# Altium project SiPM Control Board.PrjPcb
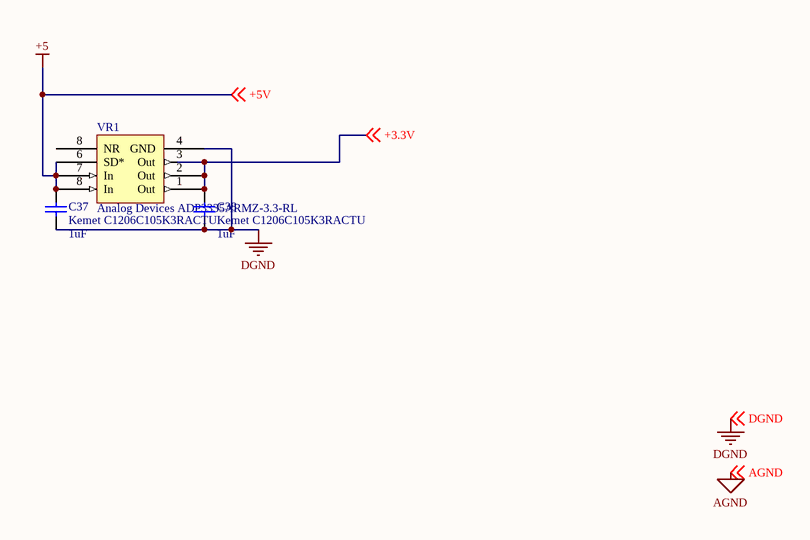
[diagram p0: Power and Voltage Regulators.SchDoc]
9 sheets, 76 parts. Net scope: global (net labels, ports and power ports of the same name join across sheets).
Board file: Prototype1.PcbDoc
Sheets:
  Power and Voltage Regulators.SchDoc
  AD5535.SchDoc
  AD5535 Power Regulators.SchDoc
  AD7314.SchDoc
  EEPROM.SchDoc
  CP2201.SchDoc
  AD7928.SchDoc
  FPGA.SchDoc
  Backplane Connector.SchDoc

## Sheet Power and Voltage Regulators.SchDoc
size A

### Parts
C37  Kemet C1206C105K3RACTU  value 1uF  [C1206]
C38  Kemet C1206C105K3RACTU  value 1uF  [C1206]
VR1  Analog Devices ADP3335ARMZ-3.3-RL  [RM-8]

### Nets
+5: C37.2 VR1.6(SD*) VR1.7(In) VR1.8(In) ; off-sheet +5V  [also labelled +5V]
DGND: C37.1 C38.1 VR1.4(GND) ; off-sheet DGND
+3.3V: C38.2 VR1.1(Out) VR1.2(Out) VR1.3(Out) ; off-sheet +3.3V

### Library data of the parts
C37 C38 = Cap: Capacitor
VR1 = ADP3335

## Sheet AD5535.SchDoc
size A
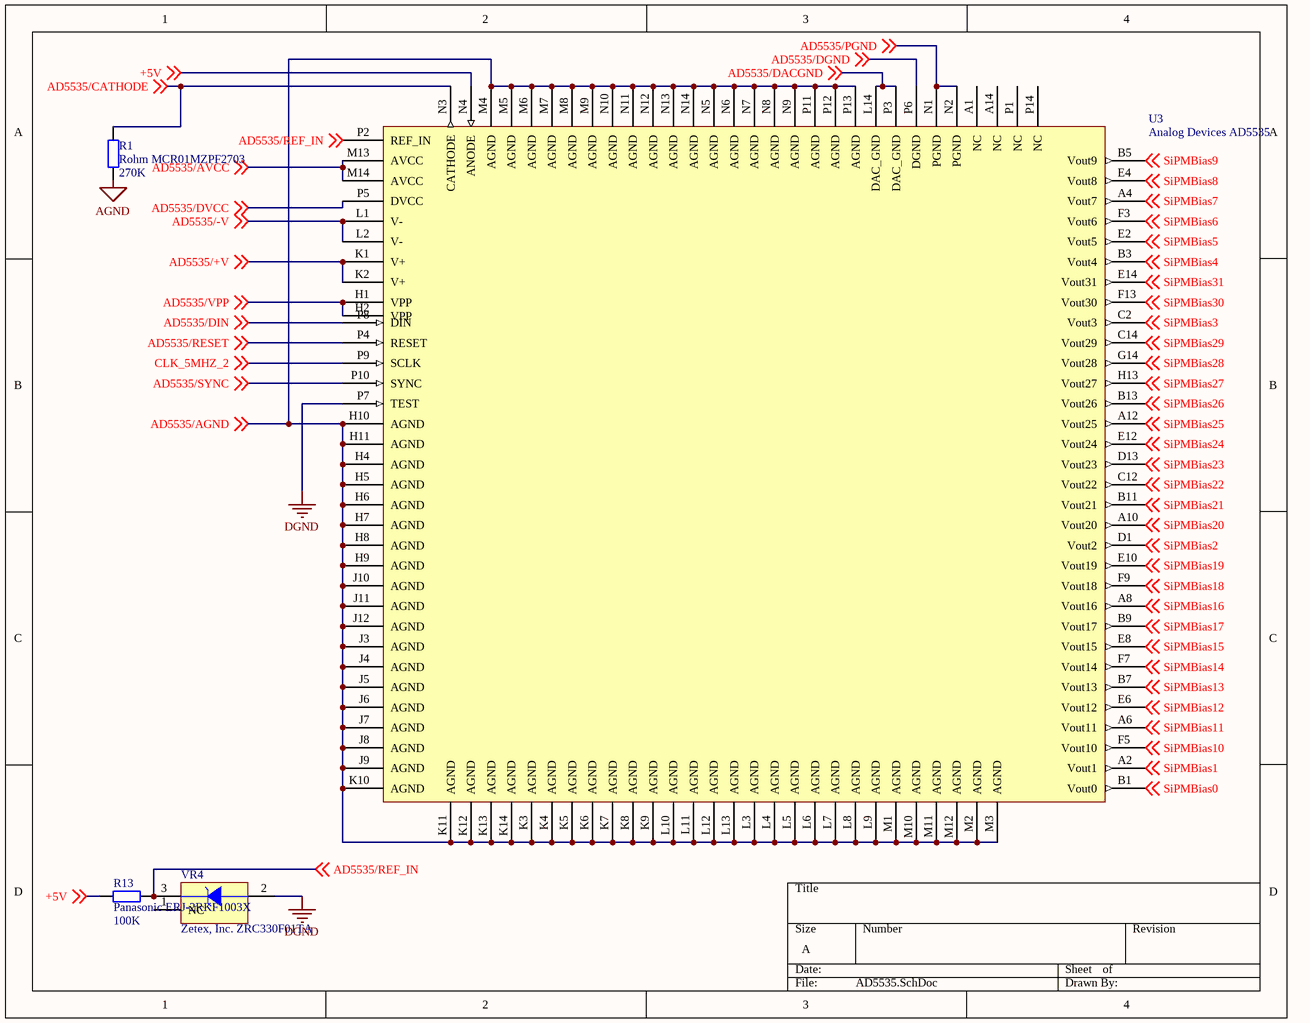
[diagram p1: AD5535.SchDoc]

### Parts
R1  Rohm MCR01MZPF2703  value 270K  [0402]
R13  Panasonic ERJ-2RKF1003X  value 100K  [1005[0402]]
U3  Analog Devices AD5535  [BC-124]
VR4  Zetex, Inc. ZRC330F01TA  [SOT23]

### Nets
+5V: R13.1 U3.K1(V+) U3.K2(V+) U3.M13(AVCC) U3.M14(AVCC) U3.N4(ANODE) U3.P5(DVCC) ; off-sheet AD5535/+V, off-sheet AD5535/AVCC, off-sheet AD5535/DVCC, off-sheet +5V  [also labelled AD5535/+V, AD5535/AVCC, AD5535/DVCC]  [project net +5]
AGND: R1.1 U3.H4(AGND) U3.H5(AGND) U3.H6(AGND) U3.H7(AGND) U3.H8(AGND) U3.H9(AGND) U3.H10(AGND) U3.H11(AGND) U3.J3(AGND) U3.J4(AGND) U3.J5(AGND) U3.J6(AGND) U3.J7(AGND) U3.J8(AGND) U3.J9(AGND) U3.J10(AGND) U3.J11(AGND) U3.J12(AGND) U3.K3(AGND) U3.K4(AGND) U3.K5(AGND) U3.K6(AGND) U3.K7(AGND) U3.K8(AGND) U3.K9(AGND) U3.K10(AGND) U3.K11(AGND) U3.K12(AGND) U3.K13(AGND) U3.K14(AGND) U3.L3(AGND) U3.L4(AGND) U3.L5(AGND) U3.L6(AGND) U3.L7(AGND) U3.L8(AGND) U3.L9(AGND) U3.L10(AGND) U3.L11(AGND) U3.L12(AGND) U3.L13(AGND) U3.L14(DAC_GND) U3.M1(AGND) U3.M2(AGND) U3.M3(AGND) U3.M4(AGND) U3.M5(AGND) U3.M6(AGND) U3.M7(AGND) U3.M8(AGND) U3.M9(AGND) U3.M10(AGND) U3.M11(AGND) U3.M12(AGND) U3.N1(PGND) U3.N2(PGND) U3.N5(AGND) U3.N6(AGND) U3.N7(AGND) U3.N8(AGND) U3.N9(AGND) U3.N10(AGND) U3.N11(AGND) U3.N12(AGND) U3.N13(AGND) U3.N14(AGND) U3.P3(DAC_GND) U3.P11(AGND) U3.P12(AGND) U3.P13(AGND) ; off-sheet AD5535/AGND, off-sheet AD5535/DACGND, off-sheet AD5535/PGND  [also labelled AD5535/AGND, AD5535/DACGND, AD5535/PGND]
DGND: U3.P6(DGND) U3.P7(TEST) VR4.2(GND) ; off-sheet AD5535/DGND  [also labelled AD5535/DGND]
AD5535/-V: U3.L1(V-) U3.L2(V-) ; off-sheet AD5535/-V  [project net -5V]
AD5535/CATHODE: R1.2 U3.N3(CATHODE) ; off-sheet AD5535/CATHODE
AD5535/DIN: U3.P8(DIN) ; off-sheet AD5535/DIN
AD5535/REF_IN: R13.2 U3.P2(REF_IN) VR4.3(VR) ; off-sheet AD5535/REF_IN
AD5535/RESET: U3.P4(RESET) ; off-sheet AD5535/RESET
AD5535/SYNC: U3.P10(SYNC) ; off-sheet AD5535/SYNC
AD5535/VPP: U3.H1(VPP) U3.H2(VPP) ; off-sheet AD5535/VPP  [project net +210V]
CLK_5MHZ_2: U3.P9(SCLK) ; off-sheet CLK_5MHZ_2
SiPMBias0: U3.B1(Vout0) ; off-sheet SiPMBias0
SiPMBias1: U3.A2(Vout1) ; off-sheet SiPMBias1
SiPMBias2: U3.D1(Vout2) ; off-sheet SiPMBias2
SiPMBias3: U3.C2(Vout3) ; off-sheet SiPMBias3
SiPMBias4: U3.B3(Vout4) ; off-sheet SiPMBias4
SiPMBias5: U3.E2(Vout5) ; off-sheet SiPMBias5
SiPMBias6: U3.F3(Vout6) ; off-sheet SiPMBias6
SiPMBias7: U3.A4(Vout7) ; off-sheet SiPMBias7
SiPMBias8: U3.E4(Vout8) ; off-sheet SiPMBias8
SiPMBias9: U3.B5(Vout9) ; off-sheet SiPMBias9
SiPMBias10: U3.F5(Vout10) ; off-sheet SiPMBias10
SiPMBias11: U3.A6(Vout11) ; off-sheet SiPMBias11
SiPMBias12: U3.E6(Vout12) ; off-sheet SiPMBias12
SiPMBias13: U3.B7(Vout13) ; off-sheet SiPMBias13
SiPMBias14: U3.F7(Vout14) ; off-sheet SiPMBias14
SiPMBias15: U3.E8(Vout15) ; off-sheet SiPMBias15
SiPMBias16: U3.A8(Vout16) ; off-sheet SiPMBias16
SiPMBias17: U3.B9(Vout17) ; off-sheet SiPMBias17
SiPMBias18: U3.F9(Vout18) ; off-sheet SiPMBias18
SiPMBias19: U3.E10(Vout19) ; off-sheet SiPMBias19
SiPMBias20: U3.A10(Vout20) ; off-sheet SiPMBias20
SiPMBias21: U3.B11(Vout21) ; off-sheet SiPMBias21
SiPMBias22: U3.C12(Vout22) ; off-sheet SiPMBias22
SiPMBias23: U3.D13(Vout23) ; off-sheet SiPMBias23
SiPMBias24: U3.E12(Vout24) ; off-sheet SiPMBias24
SiPMBias25: U3.A12(Vout25) ; off-sheet SiPMBias25
SiPMBias26: U3.B13(Vout26) ; off-sheet SiPMBias26
SiPMBias27: U3.H13(Vout27) ; off-sheet SiPMBias27
SiPMBias28: U3.G14(Vout28) ; off-sheet SiPMBias28
SiPMBias29: U3.C14(Vout29) ; off-sheet SiPMBias29
SiPMBias30: U3.F13(Vout30) ; off-sheet SiPMBias30
SiPMBias31: U3.E14(Vout31) ; off-sheet SiPMBias31

Not connected (* = marked no-connect by the designer): U3 A1(NC) A14(NC) P1(NC) P14(NC); VR4 1(NC)

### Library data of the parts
R1 R13 = Res2: Resistor
U3 = AD5535
VR4 = LM4040DIM3-2.5: Precision Micropower Shunt Voltage Reference; Note: Pin 3 must be left floating or connected to pin 2.

## Sheet AD5535 Power Regulators.SchDoc
size A
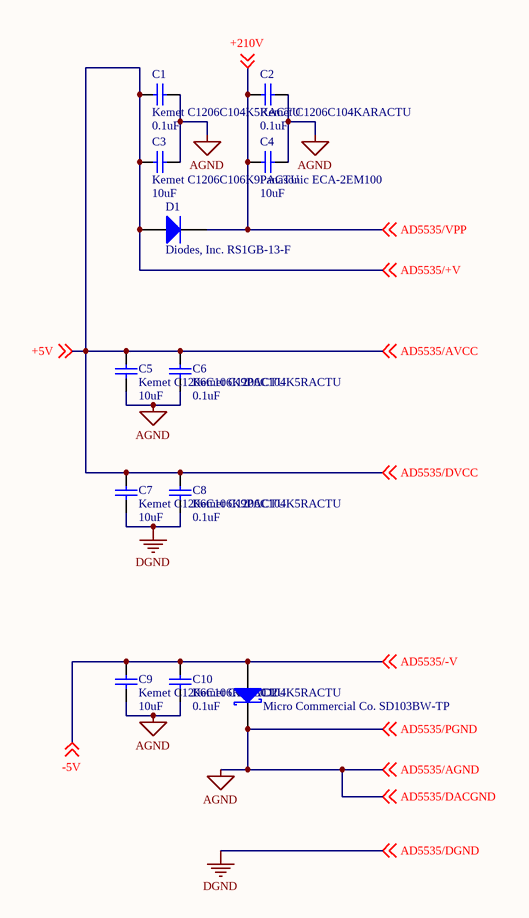
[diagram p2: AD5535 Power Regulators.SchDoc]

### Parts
C1  Kemet C1206C104K5RACTU  value 0.1uF  [C1206]
C2  Kemet C1206C104KARACTU  value 0.1uF  [C1206]
C3  Kemet C1206C106K9PACTU  value 10uF  [C1206]
C4  Panasonic ECA-2EM100  value 10uF  [CAPPR5-10x16]
C5  Kemet C1206C106K9PACTU  value 10uF  [C1206]
C6  Kemet C1206C104K5RACTU  value 0.1uF  [C1206]
C7  Kemet C1206C106K9PACTU  value 10uF  [C1206]
C8  Kemet C1206C104K5RACTU  value 0.1uF  [C1206]
C9  Kemet C1206C106K9PACTU  value 10uF  [C1206]
C10  Kemet C1206C104K5RACTU  value 0.1uF  [C1206]
D1  Diodes, Inc. RS1GB-13-F  [SMB]
D2  Micro Commercial Co. SD103BW-TP  [425]

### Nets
+5V: C1.1 C3.1 C5.2 C6.2 C7.2 C8.2 D1.1(A) ; off-sheet +5V, off-sheet AD5535/+V, off-sheet AD5535/AVCC, off-sheet AD5535/DVCC  [also labelled AD5535/+V, AD5535/AVCC, AD5535/DVCC]  [project net +5]
AGND: C1.2 C2.2 C3.2 C4.2 C5.1 C6.1 C9.1 C10.1 D2.2(K) ; off-sheet AD5535/PGND, off-sheet AD5535/AGND, off-sheet AD5535/DACGND  [also labelled AD5535/AGND, AD5535/DACGND, AD5535/PGND]
DGND: C7.1 C8.1 ; off-sheet AD5535/DGND  [also labelled AD5535/DGND]
+210V: C2.1 C4.1 D1.2(K) ; off-sheet AD5535/VPP, off-sheet +210V  [also labelled AD5535/VPP]
-5V: C9.2 C10.2 D2.1(A) ; off-sheet AD5535/-V, off-sheet -5V  [also labelled AD5535/-V]

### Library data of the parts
C1-C10 = Cap: Capacitor
D1 = Diode: Default Diode
D2 = D Schottky: Schottky Diode

## Sheet AD7314.SchDoc
size A
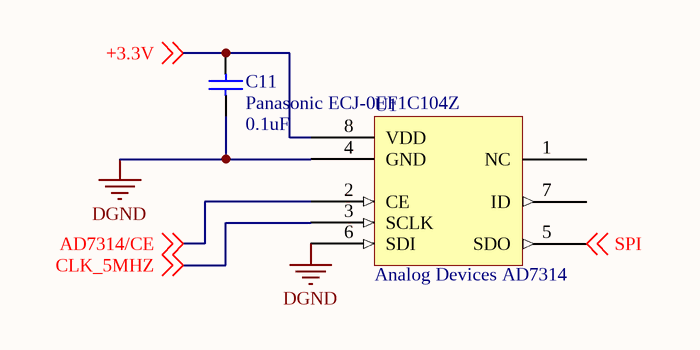
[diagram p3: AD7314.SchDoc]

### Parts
C11  Panasonic ECJ-0EF1C104Z  value 0.1uF  [0402]
U1  Analog Devices AD7314  [RM-8]

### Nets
DGND: C11.1 U1.4(GND) U1.6(SDI)
+3.3V: C11.2 U1.8(VDD) ; off-sheet +3.3V
AD7314/CE: U1.2(CE) ; off-sheet AD7314/CE
CLK_5MHZ: U1.3(SCLK) ; off-sheet CLK_5MHZ
SPI: U1.5(SDO) ; off-sheet SPI

Not connected (* = marked no-connect by the designer): U1 1(NC) 7(ID)

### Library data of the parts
C11 = Cap: Capacitor
U1 = AD7314

## Sheet EEPROM.SchDoc
size A
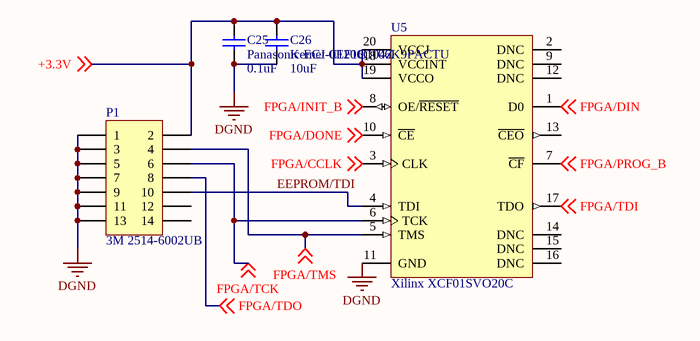
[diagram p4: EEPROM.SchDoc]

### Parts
C25  Panasonic ECJ-0EF1C104Z  value 0.1uF  [0402]
C26  Kemet C1206C106K9PACTU  value 10uF  [C1206]
P1  3M 2514-6002UB  [HDR2X7]
U5  Xilinx XCF01SVO20C  [VO20_N]

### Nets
DGND: C25.1 C26.1 P1.1 P1.3 P1.5 P1.7 P1.9 P1.11 P1.13 U5.11(GND)
+3.3V: C25.2 C26.2 P1.2 U5.18(VCCINT) U5.19(VCCO) U5.20(VCCJ) ; off-sheet +3.3V
EEPROM/TDI: P1.10 U5.4(TDI)
FPGA/CCLK: U5.3(CLK) ; off-sheet FPGA/CCLK
FPGA/DIN: U5.1(D0) ; off-sheet FPGA/DIN
FPGA/DONE: U5.10(~{CE}) ; off-sheet FPGA/DONE
FPGA/INIT_B: U5.8(OE/~{RESET}) ; off-sheet FPGA/INIT_B
FPGA/PROG_B: U5.7(~{CF}) ; off-sheet FPGA/PROG_B
FPGA/TCK: P1.6 U5.6(TCK) ; off-sheet FPGA/TCK
FPGA/TDI: U5.17(TDO) ; off-sheet FPGA/TDI
FPGA/TDO: P1.8 ; off-sheet FPGA/TDO
FPGA/TMS: P1.4 U5.5(TMS) ; off-sheet FPGA/TMS

Not connected (* = marked no-connect by the designer): P1 12 14; U5 2(DNC) 9(DNC) 12(DNC) 13(~{CEO}) 14(DNC) 15(DNC) 16(DNC)

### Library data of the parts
C25 C26 = Cap: Capacitor
P1 = Header 7X2: Header, 7-Pin, Dual row
U5 = XCF01SVO20C: XCF00S Series, Platform Flash In-System Programmable Configuration 3.3V PROM, 20-Pin TSOP, 1-Megabit, Commercial Grade

## Sheet CP2201.SchDoc
size A
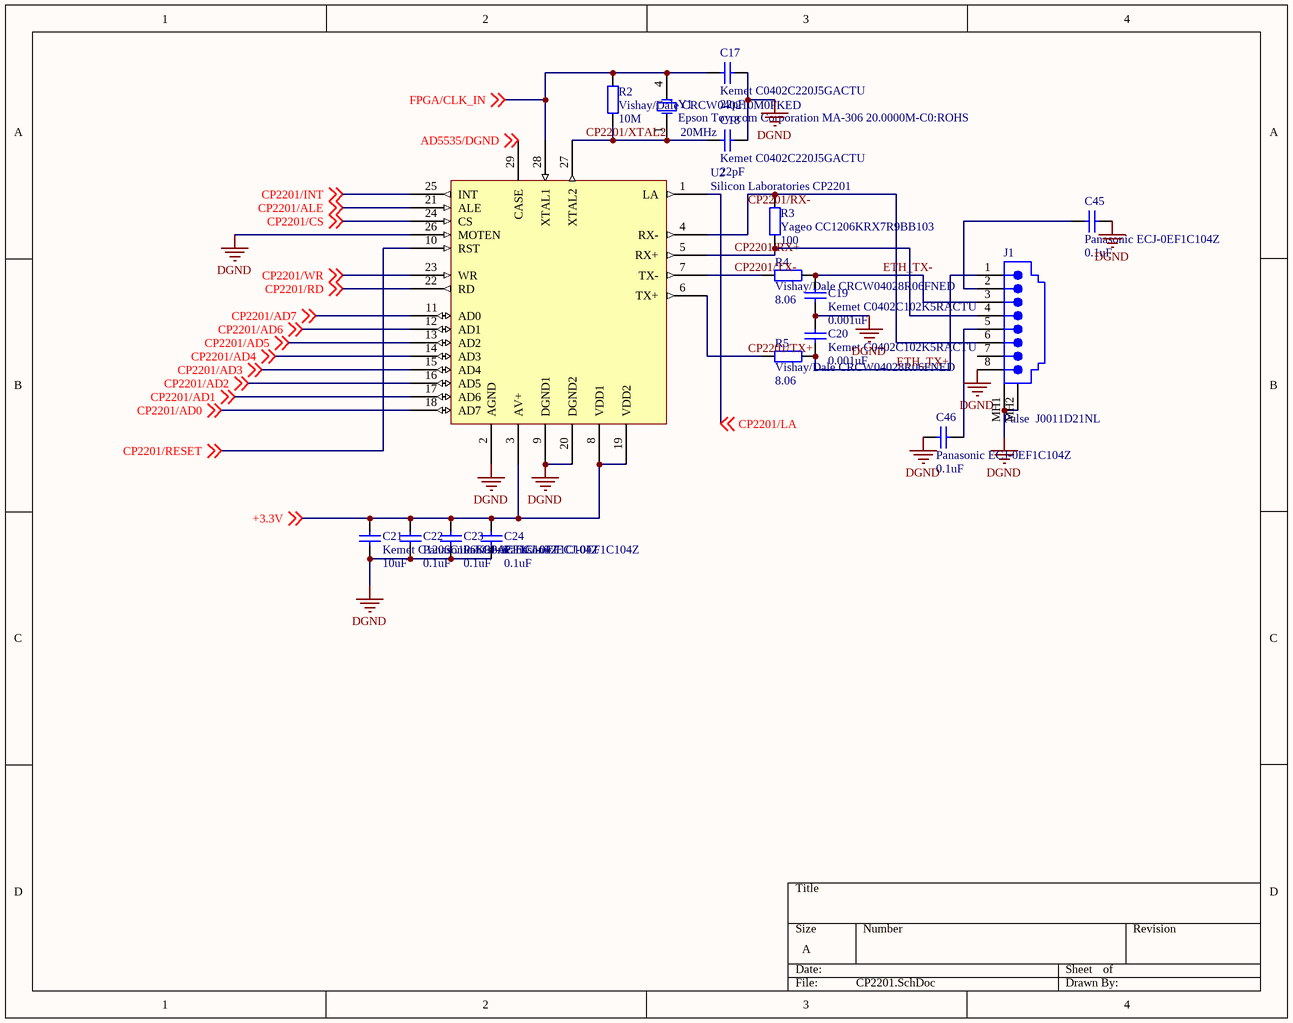
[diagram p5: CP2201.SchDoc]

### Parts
C17  Kemet C0402C220J5GACTU  value 22pF  [0402]
C18  Kemet C0402C220J5GACTU  value 22pF  [0402]
C19  Kemet C0402C102K5RACTU  value 0.001uF  [0402]
C20  Kemet C0402C102K5RACTU  value 0.001uF  [0402]
C21  Kemet C1206C106K9PACTU  value 10uF  [C1206]
C22  Panasonic ECJ-0EF1C104Z  value 0.1uF  [0402]
C23  Panasonic ECJ-0EF1C104Z  value 0.1uF  [0402]
C24  Panasonic ECJ-0EF1C104Z  value 0.1uF  [0402]
C45  Panasonic ECJ-0EF1C104Z  value 0.1uF  [0402]
C46  Panasonic ECJ-0EF1C104Z  value 0.1uF  [0402]
J1  Pulse  J0011D21NL  [43249-8925]
R2  Vishay/Dale CRCW040210M0FKED  value 10M  [1005[0402]]
R3  Yageo CC1206KRX7R9BB103  value 100  [1005[0402]]
R4  Vishay/Dale CRCW04028R06FNED  value 8.06  [1005[0402]]
R5  Vishay/Dale CRCW04028R06FNED  value 8.06  [1005[0402]]
U2  Silicon Laboratories CP2201  [QFN50P500X500-28V1N]
Y1  Epson Toyocom Corporation MA-306 20.0000M-C0:ROHS  Frequency: 20MHz  [DSO-N4]

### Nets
DGND: C17.2 C18.2 C19.1 C20.2 C21.1 C22.1 C23.1 C24.1 C45.2 C46.1 J1.8 J1.MH1(Shield) J1.MH2(Shield) U2.2(AGND) U2.9(DGND1) U2.20(DGND2) U2.26(MOTEN) U2.29(CASE) ; off-sheet AD5535/DGND  [also labelled AD5535/DGND]
+3.3V: C21.2 C22.2 C23.2 C24.2 U2.3(AV+) U2.8(VDD1) U2.19(VDD2) ; off-sheet +3.3V
CP2201/AD0: U2.18(AD7) ; off-sheet CP2201/AD0
CP2201/AD1: U2.17(AD6) ; off-sheet CP2201/AD1
CP2201/AD2: U2.16(AD5) ; off-sheet CP2201/AD2
CP2201/AD3: U2.15(AD4) ; off-sheet CP2201/AD3
CP2201/AD4: U2.14(AD3) ; off-sheet CP2201/AD4
CP2201/AD5: U2.13(AD2) ; off-sheet CP2201/AD5
CP2201/AD6: U2.12(AD1) ; off-sheet CP2201/AD6
CP2201/AD7: U2.11(AD0) ; off-sheet CP2201/AD7
CP2201/ALE: U2.21(ALE) ; off-sheet CP2201/ALE
CP2201/CS: U2.24(CS) ; off-sheet CP2201/CS
CP2201/INT: U2.25(INT) ; off-sheet CP2201/INT
CP2201/LA: U2.1(LA) ; off-sheet CP2201/LA
CP2201/RD: U2.22(RD) ; off-sheet CP2201/RD
CP2201/RESET: U2.10(RST) ; off-sheet CP2201/RESET
CP2201/RX+: J1.4 R3.1 U2.5(RX+)
CP2201/RX-: J1.6 R3.2 U2.4(RX-)
CP2201/TX+: R5.1 U2.6(TX+)
CP2201/TX-: R4.1 U2.7(TX-)
CP2201/WR: U2.23(WR) ; off-sheet CP2201/WR
CP2201/XTAL2: C18.1 R2.2 U2.27(XTAL2) Y1.1(OSC1)
ETH_TX+: C20.1 J1.1 R5.2
ETH_TX-: C19.2 J1.3 R4.2
FPGA/CLK_IN: C17.1 R2.1 U2.28(XTAL1) Y1.4(OSC2) ; off-sheet FPGA/CLK_IN
NetC45_1: C45.1 J1.2
NetC46_2: C46.2 J1.5

Not connected (* = marked no-connect by the designer): J1 7

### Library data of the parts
C17-C24 C45 C46 = Cap: Capacitor
J1 = 43249-8925: Right Angle, Low Profile, with top Panel Grounding Tabs, Shielded PCB Jack; Ports: 1; Positions/Loaded: Port1 - 8/8; PerformanceCategory: 3/4; PCB_Mounting: Thru-Hole; DrillSize: Nominal, Rounded to nearest 0.05mm; PCB_Layout: Complies with Manufacturer's Recommendation.
R2-R5 = Res2: Resistor
U2 = CP2201
Y1 = XTAL: Crystal Oscillator

## Sheet AD7928.SchDoc
size A
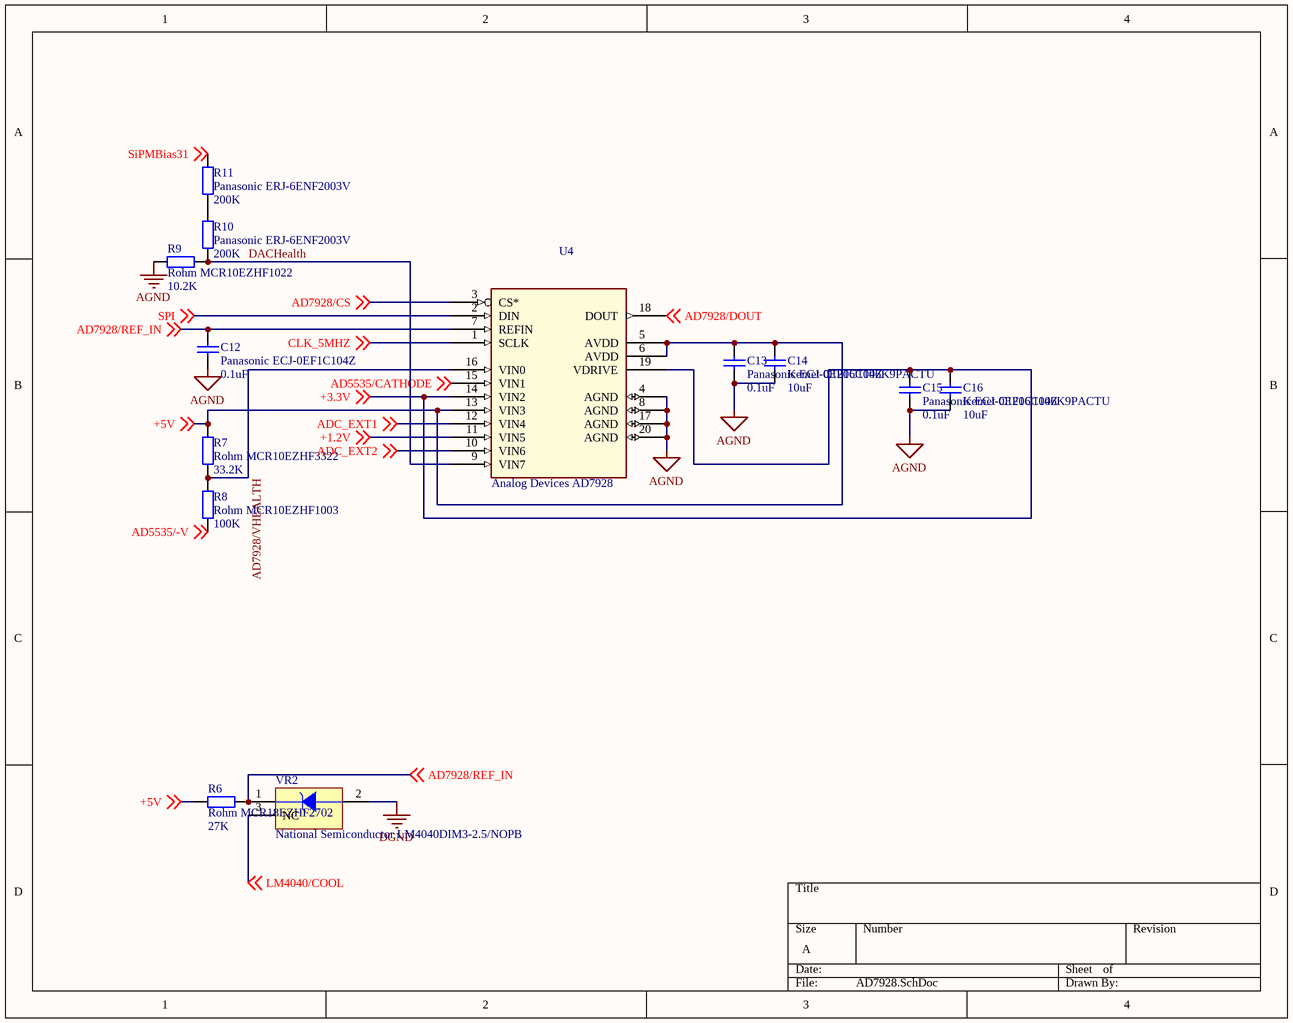
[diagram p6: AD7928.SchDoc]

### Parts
C12  Panasonic ECJ-0EF1C104Z  value 0.1uF  [0402]
C13  Panasonic ECJ-0EF1C104Z  value 0.1uF  [0402]
C14  Kemet C1206C106K9PACTU  value 10uF  [C1206]
C15  Panasonic ECJ-0EF1C104Z  value 0.1uF  [0402]
C16  Kemet C1206C106K9PACTU  value 10uF  [C1206]
R6  Rohm MCR18EZHF2702  value 27K  [3216[1206]]
R7  Rohm MCR10EZHF3322  value 33.2K  [2012[0805]]
R8  Rohm MCR10EZHF1003  value 100K  [2012[0805]]
R9  Rohm MCR10EZHF1022  value 10.2K  [2012[0805]]
R10  Panasonic ERJ-6ENF2003V  value 200K  [2012[0805]]
R11  Panasonic ERJ-6ENF2003V  value 200K  [2012[0805]]
U4  Analog Devices AD7928  [RU-20]
VR2  National Semiconductor LM4040DIM3-2.5/NOPB  [M03B]

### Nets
+5V: C13.2 C14.2 R6.1 R7.2 U4.5(AVDD) U4.6(AVDD) U4.13(VIN3) ; off-sheet +5V  [project net +5]
AGND: C12.1 C13.1 C14.1 C15.1 C16.1 R9.2 U4.4(AGND) U4.8(AGND) U4.17(AGND) U4.20(AGND)
DGND: VR2.2(V-)
+1.2V: U4.11(VIN5) ; off-sheet +1.2V
+3.3V: C15.2 C16.2 U4.14(VIN2) U4.19(VDRIVE) ; off-sheet +3.3V
AD5535/-V: R8.1 ; off-sheet AD5535/-V  [project net -5V]
AD5535/CATHODE: U4.15(VIN1) ; off-sheet AD5535/CATHODE
AD7928/CS: U4.3(CS*) ; off-sheet AD7928/CS
AD7928/DOUT: U4.18(DOUT) ; off-sheet AD7928/DOUT
AD7928/REF_IN: C12.2 R6.2 U4.7(REFIN) VR2.1(V+) ; off-sheet AD7928/REF_IN
AD7928/VHEALTH: R7.1 R8.2 U4.16(VIN0)
ADC_EXT1: U4.12(VIN4) ; off-sheet ADC_EXT1
ADC_EXT2: U4.10(VIN6) ; off-sheet ADC_EXT2
CLK_5MHZ: U4.1(SCLK) ; off-sheet CLK_5MHZ
DACHealth: R9.1 R10.1 U4.9(VIN7)
LM4040/COOL: VR2.3(NC) ; off-sheet LM4040/COOL
SiPMBias31: R11.2 ; off-sheet SiPMBias31
SPI: U4.2(DIN) ; off-sheet SPI
NetR10_2: R10.2 R11.1

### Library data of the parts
C12-C16 = Cap: Capacitor
R6-R11 = Res2: Resistor
U4 = AD7928BRU-REEL7: SlotXofY: SYM 1 OF 1
VR2 = LM4040DIM3-2.5: as VR4 on sheet AD5535

## Sheet FPGA.SchDoc
size A
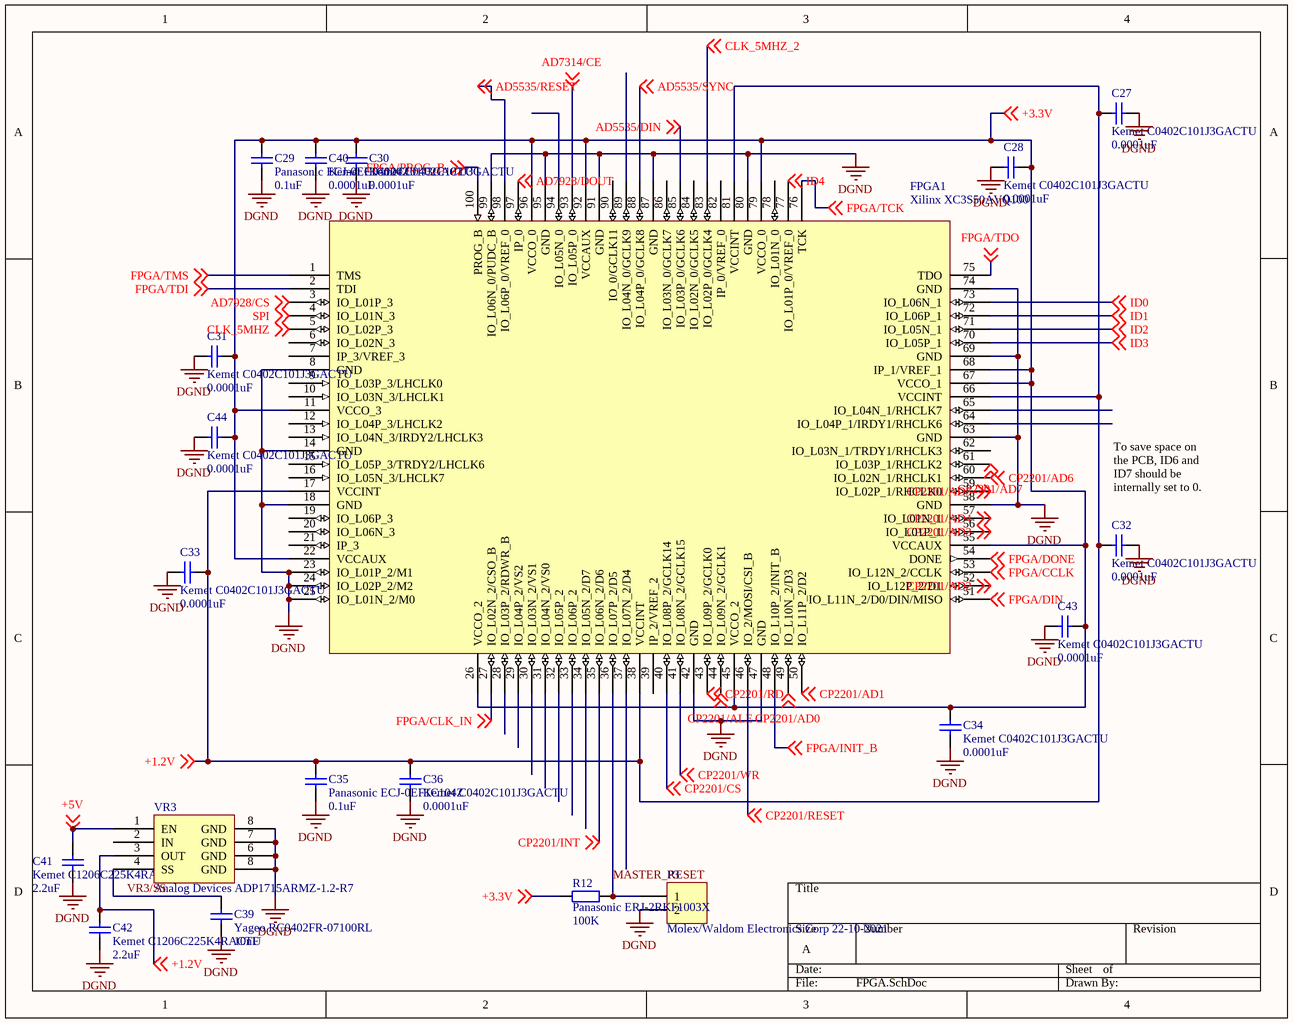
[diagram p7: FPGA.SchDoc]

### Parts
C27  Kemet C0402C101J3GACTU  value 0.0001uF  [0402]
C28  Kemet C0402C101J3GACTU  value 0.0001uF  [0402]
C29  Panasonic ECJ-0EF1C104Z  value 0.1uF  [0402]
C30  Kemet C0402C101J3GACTU  value 0.0001uF  [0402]
C31  Kemet C0402C101J3GACTU  value 0.0001uF  [0402]
C32  Kemet C0402C101J3GACTU  value 0.0001uF  [0402]
C33  Kemet C0402C101J3GACTU  value 0.0001uF  [0402]
C34  Kemet C0402C101J3GACTU  value 0.0001uF  [0402]
C35  Panasonic ECJ-0EF1C104Z  value 0.1uF  [0402]
C36  Kemet C0402C101J3GACTU  value 0.0001uF  [0402]
C39  Yageo RC0402FR-07100RL  value 10nF  [C1206]
C40  Kemet C0402C101J3GACTU  value 0.0001uF  [0402]
C41  Kemet C1206C225K4RACTU  value 2.2uF  [C1206]
C42  Kemet C1206C225K4RACTU  value 2.2uF  [C1206]
C43  Kemet C0402C101J3GACTU  value 0.0001uF  [0402]
C44  Kemet C0402C101J3GACTU  value 0.0001uF  [0402]
FPGA1  Xilinx XC3S50AVQ100  [VQ100_L]
P3  Molex/Waldom Electronics Corp 22-10-2021  [HDR1X2]
R12  Panasonic ERJ-2RKF1003X  value 100K  [1005[0402]]
VR3  Analog Devices ADP1715ARMZ-1.2-R7  [RM-8]

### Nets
+5V: C41.2 VR3.1(EN) ; off-sheet +5V  [project net +5]
DGND: C27.1 C28.1 C29.1 C30.1 C31.1 C32.1 C33.1 C34.1 C35.1 C36.1 C39.1 C40.1 C41.1 C42.1 C43.2 C44.1 FPGA1.8(GND) FPGA1.14(GND) FPGA1.18(GND) FPGA1.23(IO_L01P_2/M1) FPGA1.24(IO_L02P_2/M2) FPGA1.25(IO_L01N_2/M0) FPGA1.42(GND) FPGA1.47(GND) FPGA1.58(GND) FPGA1.63(GND) FPGA1.69(GND) FPGA1.74(GND) FPGA1.80(GND) FPGA1.87(GND) FPGA1.91(GND) FPGA1.95(GND) FPGA1.99(IO_L06N_0/PUDC_B) P3.2 VR3.6(GND) VR3.7(GND) VR3.8(GND)
+1.2V: C27.2 C32.2 C33.2 C35.2 C36.2 C42.2 FPGA1.17(VCCINT) FPGA1.38(VCCINT) FPGA1.66(VCCINT) FPGA1.81(VCCINT) VR3.3(OUT) ; off-sheet +1.2V
+3.3V: C28.2 C29.2 C30.2 C31.2 C34.2 C40.2 C43.1 C44.2 FPGA1.11(VCCO_3) FPGA1.22(VCCAUX) FPGA1.26(VCCO_2) FPGA1.45(VCCO_2) FPGA1.55(VCCAUX) FPGA1.67(VCCO_1) FPGA1.68(IP_1/VREF_1) FPGA1.79(VCCO_0) FPGA1.92(VCCAUX) FPGA1.96(VCCO_0) R12.1 ; off-sheet +3.3V
AD5535/DIN: FPGA1.85(IO_L03P_0/GCLK6) ; off-sheet AD5535/DIN
AD5535/RESET: FPGA1.98(IO_L06P_0/VREF_0) ; off-sheet AD5535/RESET
AD5535/SYNC: FPGA1.88(IO_L04P_0/GCLK8) ; off-sheet AD5535/SYNC
AD7314/CE: FPGA1.93(IO_L05P_0) ; off-sheet AD7314/CE
AD7928/CS: FPGA1.3(IO_L01P_3) ; off-sheet AD7928/CS
AD7928/DOUT: FPGA1.97(IP_0) ; off-sheet AD7928/DOUT
CLK_5MHZ: FPGA1.5(IO_L02P_3) ; off-sheet CLK_5MHZ
CLK_5MHZ_2: FPGA1.83(IO_L02P_0/GCLK4) ; off-sheet CLK_5MHZ_2
CP2201/AD0: FPGA1.49(IO_L10N_2/D3) ; off-sheet CP2201/AD0
CP2201/AD1: FPGA1.50(IO_L11P_2/D2) ; off-sheet CP2201/AD1
CP2201/AD2: FPGA1.52(IO_L12P_2/D1) ; off-sheet CP2201/AD2
CP2201/AD3: FPGA1.56(IO_L01P_1) ; off-sheet CP2201/AD3
CP2201/AD4: FPGA1.57(IO_L01N_1) ; off-sheet CP2201/AD4
CP2201/AD5: FPGA1.59(IO_L02P_1/RHCLK0) ; off-sheet CP2201/AD5
CP2201/AD6: FPGA1.60(IO_L02N_1/RHCLK1) ; off-sheet CP2201/AD6
CP2201/AD7: FPGA1.61(IO_L03P_1/RHCLK2) ; off-sheet CP2201/AD7
CP2201/ALE: FPGA1.44(IO_L09N_2/GCLK1) ; off-sheet CP2201/ALE
CP2201/CS: FPGA1.40(IO_L08P_2/GCLK14) ; off-sheet CP2201/CS
CP2201/INT: FPGA1.35(IO_L06N_2/D6) ; off-sheet CP2201/INT
CP2201/RD: FPGA1.43(IO_L09P_2/GCLK0) ; off-sheet CP2201/RD
CP2201/RESET: FPGA1.46(IO_2/MOSI/CSI_B) ; off-sheet CP2201/RESET
CP2201/WR: FPGA1.41(IO_L08N_2/GCLK15) ; off-sheet CP2201/WR
FPGA/CCLK: FPGA1.53(IO_L12N_2/CCLK) ; off-sheet FPGA/CCLK
FPGA/CLK_IN: FPGA1.27(IO_L02N_2/CSO_B) ; off-sheet FPGA/CLK_IN
FPGA/DIN: FPGA1.51(IO_L11N_2/D0/DIN/MISO) ; off-sheet FPGA/DIN
FPGA/DONE: FPGA1.54(DONE) ; off-sheet FPGA/DONE
FPGA/INIT_B: FPGA1.48(IO_L10P_2/INIT_B) ; off-sheet FPGA/INIT_B
FPGA/PROG_B: FPGA1.100(PROG_B) ; off-sheet FPGA/PROG_B
FPGA/TCK: FPGA1.76(TCK) ; off-sheet FPGA/TCK
FPGA/TDI: FPGA1.2(TDI) ; off-sheet FPGA/TDI
FPGA/TDO: FPGA1.75(TDO) ; off-sheet FPGA/TDO
FPGA/TMS: FPGA1.1(TMS) ; off-sheet FPGA/TMS
ID0: FPGA1.73(IO_L06N_1) ; off-sheet ID0
ID1: FPGA1.72(IO_L06P_1) ; off-sheet ID1
ID2: FPGA1.71(IO_L05N_1) ; off-sheet ID2
ID3: FPGA1.70(IO_L05P_1) ; off-sheet ID3
ID4: FPGA1.77(IO_L01P_0/VREF_0) ; off-sheet ID4
MASTER_RESET: FPGA1.36(IO_L07P_2/D5) P3.1 R12.2
SPI: FPGA1.4(IO_L01N_3) ; off-sheet SPI
VR3/SS: C39.2 VR3.4(SS)

Not connected (* = marked no-connect by the designer): FPGA1 6(IO_L02N_3) 7(IP_3/VREF_3) 9(IO_L03P_3/LHCLK0) 10(IO_L03N_3/LHCLK1) 12(IO_L04P_3/LHCLK2) 13(IO_L04N_3/IRDY2/LHCLK3) 15(IO_L05P_3/TRDY2/LHCLK6) 16(IO_L05N_3/LHCLK7) 19(IO_L06P_3) 20(IO_L06N_3) 21(IP_3) 28(IO_L03P_2/RDWR_B) 29(IO_L04P_2/VS2) 30(IO_L03N_2/VS1) 31(IO_L04N_2/VS0) 32(IO_L05P_2) 33(IO_L06P_2) 34(IO_L05N_2/D7) 37(IO_L07N_2/D4) 39(IP_2/VREF_2) 62(IO_L03N_1/TRDY1/RHCLK3) 64(IO_L04P_1/IRDY1/RHCLK6) 65(IO_L04N_1/RHCLK7) 78(IO_L01N_0) 82(IP_0/VREF_0) 84(IO_L02N_0/GCLK5) 86(IO_L03N_0/GCLK7) 89(IO_L04N_0/GCLK9) 90(IO_0/GCLK11) 94(IO_L05N_0); VR3 2(IN)

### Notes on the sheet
- (near C32) To save space on the PCB, ID6 and ID7 should be internally set to 0.

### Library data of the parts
C27-C36 C39-C44 = Cap: Capacitor
FPGA1 = XC3S50AVQ100
P3 = Header 2: Header, 2-Pin
R12 = Res2: Resistor
VR3 = ADP1715

## Sheet Backplane Connector.SchDoc
size A
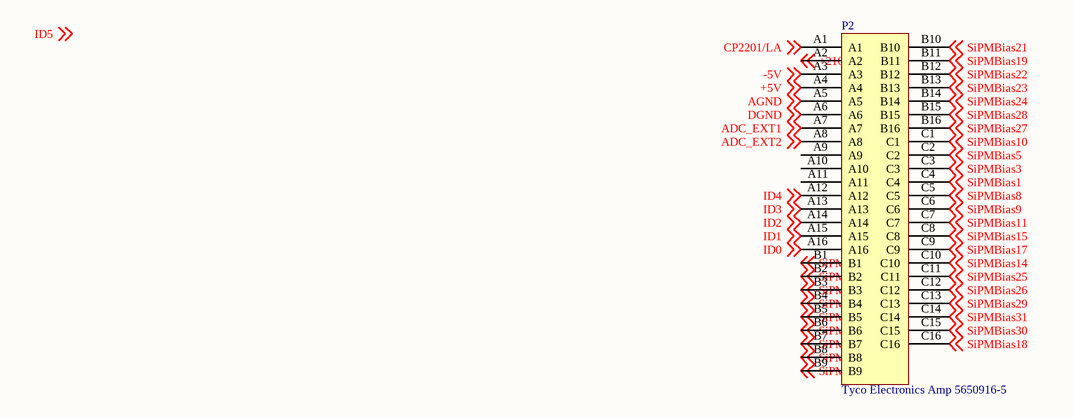
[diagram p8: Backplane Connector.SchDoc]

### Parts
P2  Tyco Electronics Amp 5650916-5  [EURO2.54-2H48]

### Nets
+5V: P2.A4 ; off-sheet +5V  [project net +5]
AGND: P2.A5 ; off-sheet AGND
DGND: P2.A6 ; off-sheet DGND
+210V: P2.A2 ; off-sheet +210V
-5V: P2.A3 ; off-sheet -5V
ADC_EXT1: P2.A7 ; off-sheet ADC_EXT1
ADC_EXT2: P2.A8 ; off-sheet ADC_EXT2
CP2201/LA: P2.A1 ; off-sheet CP2201/LA
ID0: P2.A16 ; off-sheet ID0
ID1: P2.A15 ; off-sheet ID1
ID2: P2.A14 ; off-sheet ID2
ID3: P2.A13 ; off-sheet ID3
ID4: P2.A12 ; off-sheet ID4
SiPMBias0: P2.B3 ; off-sheet SiPMBias0
SiPMBias1: P2.C4 ; off-sheet SiPMBias1
SiPMBias2: P2.B2 ; off-sheet SiPMBias2
SiPMBias3: P2.C3 ; off-sheet SiPMBias3
SiPMBias4: P2.B4 ; off-sheet SiPMBias4
SiPMBias5: P2.C2 ; off-sheet SiPMBias5
SiPMBias6: P2.B1 ; off-sheet SiPMBias6
SiPMBias7: P2.B5 ; off-sheet SiPMBias7
SiPMBias8: P2.C5 ; off-sheet SiPMBias8
SiPMBias9: P2.C6 ; off-sheet SiPMBias9
SiPMBias10: P2.C1 ; off-sheet SiPMBias10
SiPMBias11: P2.C7 ; off-sheet SiPMBias11
SiPMBias12: P2.B6 ; off-sheet SiPMBias12
SiPMBias13: P2.B7 ; off-sheet SiPMBias13
SiPMBias14: P2.C10 ; off-sheet SiPMBias14
SiPMBias15: P2.C8 ; off-sheet SiPMBias15
SiPMBias16: P2.B8 ; off-sheet SiPMBias16
SiPMBias17: P2.C9 ; off-sheet SiPMBias17
SiPMBias18: P2.C16 ; off-sheet SiPMBias18
SiPMBias19: P2.B11 ; off-sheet SiPMBias19
SiPMBias20: P2.B9 ; off-sheet SiPMBias20
SiPMBias21: P2.B10 ; off-sheet SiPMBias21
SiPMBias22: P2.B12 ; off-sheet SiPMBias22
SiPMBias23: P2.B13 ; off-sheet SiPMBias23
SiPMBias24: P2.B14 ; off-sheet SiPMBias24
SiPMBias25: P2.C11 ; off-sheet SiPMBias25
SiPMBias26: P2.C12 ; off-sheet SiPMBias26
SiPMBias27: P2.B16 ; off-sheet SiPMBias27
SiPMBias28: P2.B15 ; off-sheet SiPMBias28
SiPMBias29: P2.C13 ; off-sheet SiPMBias29
SiPMBias30: P2.C15 ; off-sheet SiPMBias30
SiPMBias31: P2.C14 ; off-sheet SiPMBias31

Not connected (* = marked no-connect by the designer): P2 A9 A10 A11

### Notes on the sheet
- Labels drawn without touching a wire or pin: ID5

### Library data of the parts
P2 = DIN41612 48 Connector

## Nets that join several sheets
+5: Power and Voltage Regulators (C37.2 VR1.6 VR1.7 VR1.8), AD5535 (7 pins), AD5535 Power Regulators (7 pins), AD7928 (7 pins), FPGA (C41.2 VR3.1), Backplane Connector (P2.A4)
AGND: AD5535 (71 pins), AD5535 Power Regulators (9 pins), AD7928 (10 pins), Backplane Connector (P2.A5)
DGND: Power and Voltage Regulators (C37.1 C38.1 VR1.4), AD5535 (U3.P6 U3.P7 VR4.2), AD5535 Power Regulators (C7.1 C8.1), AD7314 (C11.1 U1.4 U1.6), EEPROM (10 pins), CP2201 (18 pins), AD7928 (VR2.2), FPGA (37 pins), Backplane Connector (P2.A6)
+1.2V: AD7928 (U4.11), FPGA (11 pins)
+3.3V: Power and Voltage Regulators (C38.2 VR1.1 VR1.2 VR1.3), AD7314 (C11.2 U1.8), EEPROM (6 pins), CP2201 (7 pins), AD7928 (C15.2 C16.2 U4.14 U4.19), FPGA (19 pins)
+210V: AD5535 (U3.H1 U3.H2), AD5535 Power Regulators (C2.1 C4.1 D1.2), Backplane Connector (P2.A2)
-5V: AD5535 (U3.L1 U3.L2), AD5535 Power Regulators (C9.2 C10.2 D2.1), AD7928 (R8.1), Backplane Connector (P2.A3)
AD5535/CATHODE: AD5535 (R1.2 U3.N3), AD7928 (U4.15)
AD5535/DIN: AD5535 (U3.P8), FPGA (FPGA1.85)
AD5535/RESET: AD5535 (U3.P4), FPGA (FPGA1.98)
AD5535/SYNC: AD5535 (U3.P10), FPGA (FPGA1.88)
AD7314/CE: AD7314 (U1.2), FPGA (FPGA1.93)
AD7928/CS: AD7928 (U4.3), FPGA (FPGA1.3)
AD7928/DOUT: AD7928 (U4.18), FPGA (FPGA1.97)
ADC_EXT1: AD7928 (U4.12), Backplane Connector (P2.A7)
ADC_EXT2: AD7928 (U4.10), Backplane Connector (P2.A8)
CLK_5MHZ: AD7314 (U1.3), AD7928 (U4.1), FPGA (FPGA1.5)
CLK_5MHZ_2: AD5535 (U3.P9), FPGA (FPGA1.83)
CP2201/AD0: CP2201 (U2.18), FPGA (FPGA1.49)
CP2201/AD1: CP2201 (U2.17), FPGA (FPGA1.50)
CP2201/AD2: CP2201 (U2.16), FPGA (FPGA1.52)
CP2201/AD3: CP2201 (U2.15), FPGA (FPGA1.56)
CP2201/AD4: CP2201 (U2.14), FPGA (FPGA1.57)
CP2201/AD5: CP2201 (U2.13), FPGA (FPGA1.59)
CP2201/AD6: CP2201 (U2.12), FPGA (FPGA1.60)
CP2201/AD7: CP2201 (U2.11), FPGA (FPGA1.61)
CP2201/ALE: CP2201 (U2.21), FPGA (FPGA1.44)
CP2201/CS: CP2201 (U2.24), FPGA (FPGA1.40)
CP2201/INT: CP2201 (U2.25), FPGA (FPGA1.35)
CP2201/LA: CP2201 (U2.1), Backplane Connector (P2.A1)
CP2201/RD: CP2201 (U2.22), FPGA (FPGA1.43)
CP2201/RESET: CP2201 (U2.10), FPGA (FPGA1.46)
CP2201/WR: CP2201 (U2.23), FPGA (FPGA1.41)
FPGA/CCLK: EEPROM (U5.3), FPGA (FPGA1.53)
FPGA/CLK_IN: CP2201 (C17.1 R2.1 U2.28 Y1.4), FPGA (FPGA1.27)
FPGA/DIN: EEPROM (U5.1), FPGA (FPGA1.51)
FPGA/DONE: EEPROM (U5.10), FPGA (FPGA1.54)
FPGA/INIT_B: EEPROM (U5.8), FPGA (FPGA1.48)
FPGA/PROG_B: EEPROM (U5.7), FPGA (FPGA1.100)
FPGA/TCK: EEPROM (P1.6 U5.6), FPGA (FPGA1.76)
FPGA/TDI: EEPROM (U5.17), FPGA (FPGA1.2)
FPGA/TDO: EEPROM (P1.8), FPGA (FPGA1.75)
FPGA/TMS: EEPROM (P1.4 U5.5), FPGA (FPGA1.1)
ID0: FPGA (FPGA1.73), Backplane Connector (P2.A16)
ID1: FPGA (FPGA1.72), Backplane Connector (P2.A15)
ID2: FPGA (FPGA1.71), Backplane Connector (P2.A14)
ID3: FPGA (FPGA1.70), Backplane Connector (P2.A13)
ID4: FPGA (FPGA1.77), Backplane Connector (P2.A12)
SiPMBias0: AD5535 (U3.B1), Backplane Connector (P2.B3)
SiPMBias1: AD5535 (U3.A2), Backplane Connector (P2.C4)
SiPMBias2: AD5535 (U3.D1), Backplane Connector (P2.B2)
SiPMBias3: AD5535 (U3.C2), Backplane Connector (P2.C3)
SiPMBias4: AD5535 (U3.B3), Backplane Connector (P2.B4)
SiPMBias5: AD5535 (U3.E2), Backplane Connector (P2.C2)
SiPMBias6: AD5535 (U3.F3), Backplane Connector (P2.B1)
SiPMBias7: AD5535 (U3.A4), Backplane Connector (P2.B5)
SiPMBias8: AD5535 (U3.E4), Backplane Connector (P2.C5)
SiPMBias9: AD5535 (U3.B5), Backplane Connector (P2.C6)
SiPMBias10: AD5535 (U3.F5), Backplane Connector (P2.C1)
SiPMBias11: AD5535 (U3.A6), Backplane Connector (P2.C7)
SiPMBias12: AD5535 (U3.E6), Backplane Connector (P2.B6)
SiPMBias13: AD5535 (U3.B7), Backplane Connector (P2.B7)
SiPMBias14: AD5535 (U3.F7), Backplane Connector (P2.C10)
SiPMBias15: AD5535 (U3.E8), Backplane Connector (P2.C8)
SiPMBias16: AD5535 (U3.A8), Backplane Connector (P2.B8)
SiPMBias17: AD5535 (U3.B9), Backplane Connector (P2.C9)
SiPMBias18: AD5535 (U3.F9), Backplane Connector (P2.C16)
SiPMBias19: AD5535 (U3.E10), Backplane Connector (P2.B11)
SiPMBias20: AD5535 (U3.A10), Backplane Connector (P2.B9)
SiPMBias21: AD5535 (U3.B11), Backplane Connector (P2.B10)
SiPMBias22: AD5535 (U3.C12), Backplane Connector (P2.B12)
SiPMBias23: AD5535 (U3.D13), Backplane Connector (P2.B13)
SiPMBias24: AD5535 (U3.E12), Backplane Connector (P2.B14)
SiPMBias25: AD5535 (U3.A12), Backplane Connector (P2.C11)
SiPMBias26: AD5535 (U3.B13), Backplane Connector (P2.C12)
SiPMBias27: AD5535 (U3.H13), Backplane Connector (P2.B16)
SiPMBias28: AD5535 (U3.G14), Backplane Connector (P2.B15)
SiPMBias29: AD5535 (U3.C14), Backplane Connector (P2.C13)
SiPMBias30: AD5535 (U3.F13), Backplane Connector (P2.C15)
SiPMBias31: AD5535 (U3.E14), AD7928 (R11.2), Backplane Connector (P2.C14)
SPI: AD7314 (U1.5), AD7928 (U4.2), FPGA (FPGA1.4)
